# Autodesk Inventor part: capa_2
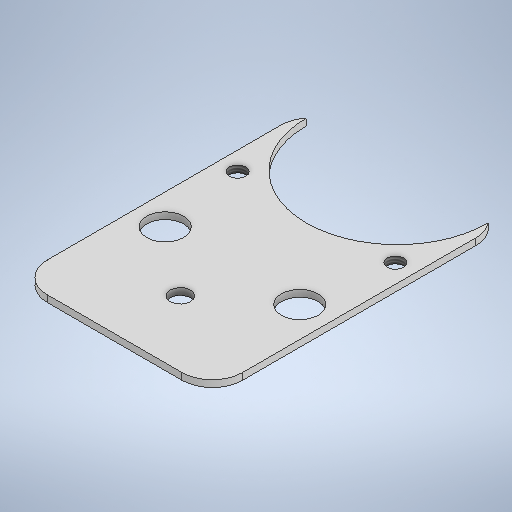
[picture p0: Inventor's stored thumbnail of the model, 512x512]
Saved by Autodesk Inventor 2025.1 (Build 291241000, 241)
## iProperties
Created: 2026-01
Part Number: capa_2
Material: Genérico
Document SubType Name: Modeling
Designer: Usuario
Density: 1 g/cm^3
Appearance: Valor por defecto
Author: Usuario
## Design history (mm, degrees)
sketch "Boceto1" dims "d19" = 6 (= D_interno_polea_metal), "d38" = 4.85 (= d_screw_union)
  geometry: L1 (0, 0)-(-58, 0); L2 (-58, 0)-(-58, -84); L3 (0, -84)-(0, 0); L4 (-29, 0)-(-29, -16.5); L5 (-58, -84)-(-56, -84); L6 (0, -84)-(-2, -84); A1 r 27 centre (-29, -84) between (-2, -84) and (-56, -84); 1 further point
  constraints: 12 end point, 3 horizontal, 2 point on circle, 1 centre point, 1 midpoint, 1 parallel, 1 perpendicular, 1 vertical, 1 vertical alignment, 2 other
  dimensions: "d3" = 58 distance of L3.start L2.end (= base); "d10" = 84 distance of L2.end L1.end (= altura); "d25" = 54 diameter of A1 (= 2 x R_polea_driven)
extrude "c2" new body sketch "Boceto1" distance "d22" = 2 (= grosor_capa_inter); taper "d24" = 0 deg
fillet "Empalme1" dims "d27" = 9
fillet "Empalme2" dims "d28" = 9
fillet "Empalme3" dims "d29" = 9
node "Plano de trabajo1"
sketch "Boceto2"
  geometry: L1 (84, 0)-(49, 0); L2 (5.657, 0)-(75, 0) reference; L3 (49, 0)-(49, 9); L4 (84, 9)-(84, 49) reference; L5 (84, 29)-(76.891, 29); C1 r 5.5 at (49, 9); C2 r 5.5 at (49, 49)
  constraints: 6 end point, 2 centre point, 1 coincident, 1 horizontal, 1 midpoint, 1 point on line, 1 symmetric about line, 1 vertical, 1 other
  dimensions: "d30" = 35 distance of L1.start L1.end; "d31" = 9 distance of L1.end L3.end; "d32" = 11 diameter of C1
extrude "entradaAcoples" cut sketch "Boceto2" extent not by distance; stored distance "d33" = 0; taper "d34" = 0 deg
sketch "Boceto3"
  geometry: L1 (84, 9)-(84, 49) reference; L2 (84, 29)-(24, 29); L3 (24, 29)-(24, 5.565); C1 r 2.425 at (24, 5.565); C2 r 2.425 at (24, 52.435); 1 further point
  constraints: 4 end point, 2 centre point, 1 coincident, 1 horizontal, 1 midpoint, 1 point on line, 1 symmetric about line, 1 vertical, 1 other
  dimensions: "d36" = 60 distance of L2.start L2.end (computed from altura); "d37" = 23.435 distance of L3.start L3.end (= 0.5 x dist_between_screws); "d38" = 4.85 diameter of C1 (= d_screw_union)
extrude "tornillos" cut sketch "Boceto3" extent not by distance; stored distance "d39" = 0; taper "d40" = 0 deg
feature "Rosca1" dims "d41" = 2, "d42" = 0
node "Sólido1"
feature "Rosca2" dims "d45" = 2, "d46" = 0
other parameters: "R_polea_driven" = 27 [user parameter; used in 4 equation terms], "D_polea_metal" = 21 [user parameter; used in 5 equation terms], "margen_canal" = 4 [user parameter; used in 5 equation terms], "d2" = 1 [user parameter], "d4" = 18.5 (= 0.5 x D_polea_metal + 2 x margen_canal) [user parameter], "d5" = 29 (= D_polea_metal + 2 x margen_canal) [user parameter], "d6" = 27 (= R_polea_driven) [user parameter], "d7" = 21 (= D_polea_metal) [user parameter], "d8" = 9 [user parameter], "d9" = 5 [user parameter], "d13" = 4 (= margen_canal) [user parameter], "espesor_polea_metalica" = 7 [user parameter; used in 1 equation term], "d14" = 7 (= espesor_polea_metalica) [user parameter], "d15" = 0 [user parameter], "margen_cara_lateral" = 2.5 [user parameter; used in 1 equation term], "d16" = 2.5 (= margen_cara_lateral) [user parameter], "d17" = 0 [user parameter], "D_interno_polea_metal" = 6 [user parameter; used in 2 equation terms], "d18" = 6 (= D_interno_polea_metal) [user parameter], "d21" = 5 (computed from margen_canal) [user parameter], "d23" = 0 [user parameter], "base" = 58 (computed from R_polea_driven) [user parameter; used in 2 equation terms], "dist_poleas" = 57.5 (computed from D_polea_metal, R_polea_driven) [user parameter; used in 1 equation term], "d1" = 58 (= base) [user parameter], "altura" = 84 (computed from dist_poleas, D_polea_metal, margen_canal) [user parameter; used in 3 equation terms], "d0" = 84 (= altura) [user parameter], "grosor_capa_inter" = 2 [user parameter; used in 1 equation term], "d_screw_union" = 4.85 [user parameter; used in 1 equation term], "dist_between_screws" = 46.87 [user parameter; used in 1 equation term]
